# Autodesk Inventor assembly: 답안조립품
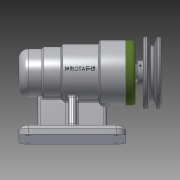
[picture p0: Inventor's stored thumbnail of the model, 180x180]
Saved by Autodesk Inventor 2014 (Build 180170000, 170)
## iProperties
Created: 2016-06
Part Number: 답안조립품
Document SubType Name: Assembly
Designer: 601-
Author: 601-
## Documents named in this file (11)
- C:\Users\601-\Desktop\460608V1027\답안조립품.iam
- C:\Users\601-\Desktop\460608V1027\본체.ipt
- C:\Users\601-\Desktop\460608V1027\축.ipt
- C:\Users\601-\Desktop\460608V1027\오일 실.ipt
- C:\Users\601-\Desktop\460608V1027\어댑터슬리브.ipt
- C:\Users\601-\Desktop\460608V1027\멈춤나사 M3x8.ipt
- C:\Users\601-\Desktop\460608V1027\베어링 51202.ipt
- C:\Users\601-\Desktop\460608V1027\키 5 x 5 x 16.ipt
- C:\Users\601-\Desktop\460608V1027\V벨트풀리.ipt
- C:\Users\601-\Desktop\460608V1027\커버.ipt
- C:\Users\601-\Desktop\460608V1027\볼트 M4 x 12.ipt
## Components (5 placed, 2 different names)
1. V벨트풀리:1 — Mate:13, Mate:14, Mate:15
2. ISO 4762 M4 x 12:1 — Mate:21, Mate:27
3. ISO 4762 M4 x 12:2 — Mate:22, Mate:25
4. ISO 4762 M4 x 12:3 — Mate:24, Mate:28
5. ISO 4762 M4 x 12:4 — Mate:23, Mate:26
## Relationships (11: Mate 11)
- Mate:13: V벨트풀리:1
- Mate:14: V벨트풀리:1
- Mate:15: V벨트풀리:1
- Mate:21: ISO 4762 M4 x 12:1
- Mate:22: ISO 4762 M4 x 12:2
- Mate:23: ISO 4762 M4 x 12:4
- Mate:24: ISO 4762 M4 x 12:3
- Mate:25: ISO 4762 M4 x 12:2
- Mate:26: ISO 4762 M4 x 12:4
- Mate:27: ISO 4762 M4 x 12:1
- Mate:28: ISO 4762 M4 x 12:3
